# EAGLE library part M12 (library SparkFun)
Header 12 Standard 12-pin 0.1" header. Use with straight break away headers (SKU : PType-HD), right angle break away headers (PType-HD-RightAngle), swiss pins (PType-30F), machine pins (PType-MP), and female headers (PType-FH). Molex polarized connector foot print use with SKU : Con-Hdr with associated crimp pins and housings.
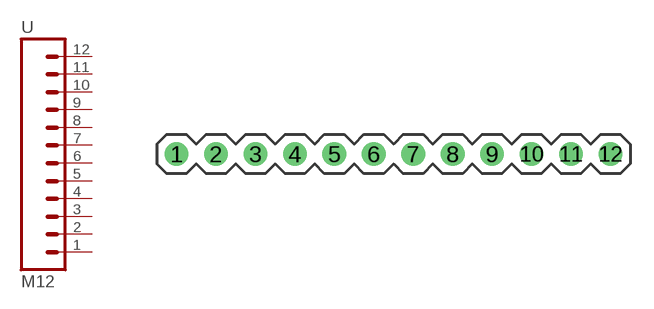
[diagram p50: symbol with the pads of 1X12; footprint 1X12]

Designator prefix -

## M12PTH  [1X12]
1  1  pas
2  2  pas
3  3  pas
4  4  pas
5  5  pas
6  6  pas
7  7  pas
8  8  pas
9  9  pas
10  10  pas
11  11  pas
12  12  pas

## Footprint 1X12 (pad centres in mm)
drill 1.016 round: 1 0,0; 2 2.54,0; 3 5.08,0; 4 7.62,0; 5 10.16,0; 6 12.7,0; 7 15.24,0; 8 17.78,0; 9 20.32,0; 10 22.86,0; 11 25.4,0; 12 27.94,0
